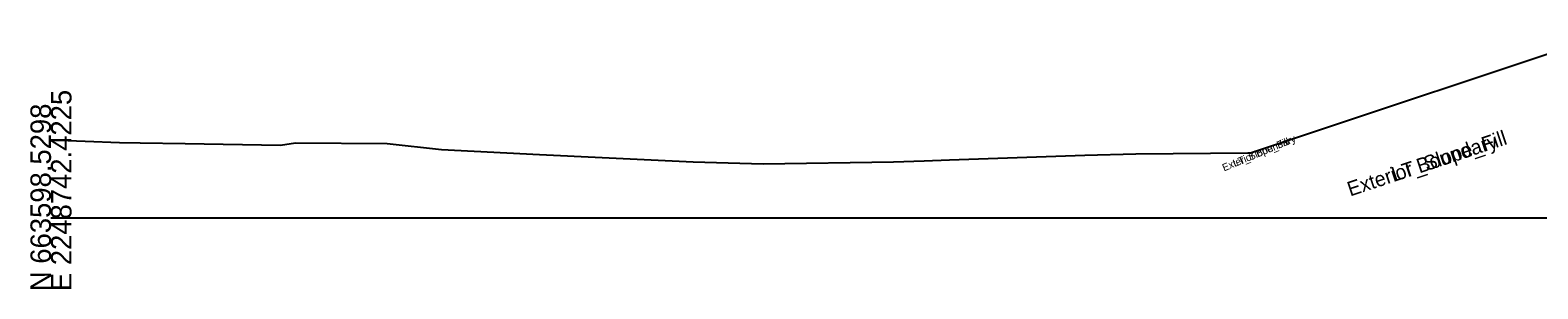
# Model space of a CAD drawing. Extents: x -26 to 2603, y -10 to 9566.
# Drawn here: x 997.2 to 1203, y 2990.3 to 3025.6 of the extents above; entities that cross this region are included whole.
import ezdxf

# ---------------------------------------------------------------- set-up
doc = ezdxf.new("R2010")
doc.units = 0
for name, color, linetype in [('Default', 7, 'Continuous'), ('Exist Cross Section Cell', 7, 'Continuous'), ('Exist XS Ground Line', 7, 'Continuous'), ('Scratch_Level_9', 7, 'Continuous')]:
    doc.layers.add(name, color=color, linetype=linetype)

msp = doc.modelspace()

# ---------------------------------------------------------------- linework, layer by layer
at = {"layer": 'Exist Cross Section Cell'}
msp.add_line((1000, 3000), (1300, 3000), dxfattribs=at)
at = {"layer": 'Exist XS Ground Line'}
for p, q in [((1000, 3010.64), (1009.37, 3010.3)), ((1009.37, 3010.3), (1012.17, 3010.27)), ((1012.17, 3010.27), (1018.32, 3010.14)), ((1018.32, 3010.14), (1031.34, 3009.93)), ((1031.34, 3009.93), (1033.38, 3010.23)), ((1033.38, 3010.23), (1045.92, 3010.16)), ((1045.92, 3010.16), (1053.3, 3009.35)), ((1053.3, 3009.35), (1066.68, 3008.67)), ((1066.68, 3008.67), (1075.27, 3008.24)), ((1075.27, 3008.24), (1087.69, 3007.67)), ((1087.69, 3007.67), (1097.24, 3007.36)), ((1097.24, 3007.36), (1115.04, 3007.67)), ((1115.04, 3007.67), (1119.2, 3007.78)), ((1119.2, 3007.78), (1122.67, 3007.91)), ((1122.67, 3007.91), (1141.17, 3008.55)), ((1141.17, 3008.55), (1148.11, 3008.75)), ((1148.11, 3008.75), (1163.4, 3008.9)), ((1163.4, 3008.9), (1163.9, 3008.88))]:
    msp.add_line(p, q, dxfattribs=at)
msp.add_lwpolyline([(1214.18, 3025.64), (1163.9, 3008.88)], dxfattribs=at)

# ---------------------------------------------------------------- texts
at = {"layer": 'Default'}
msp.add_text('-', height=0.0001, dxfattribs=at).set_placement((1000, 3000))
msp.add_text('-', height=0.0001, dxfattribs=at).set_placement((1000, 3000))
msp.add_text('-', height=0.0001, dxfattribs=at).set_placement((1000, 3000))
msp.add_text('-', height=0.0001, dxfattribs=at).set_placement((1000, 3000))
msp.add_text('-', height=0.0001, dxfattribs=at).set_placement((1000, 3000))
at = {"layer": 'Exist Cross Section Cell'}
for s, p in [('E 2248742.4225', (1002.8, 2990)), ('N 663598.5298', (1000, 2990))]:
    msp.add_text(s, height=2.8, rotation=90, dxfattribs=at).set_placement(p)
at = {"layer": 'Scratch_Level_9'}
for s, height, rotation, p in [('LT_Slope_Fill', 2, 18.4332, (1183.44, 3004.93)), ('LT_Slope_Fill', 2, 18.4332, (1183.44, 3004.93)), ('Exterior Boundary', 1, 22.5575, (1160.17, 3006.34)), ('LT_Slope_Fill', 1, 22.5575, (1161.63, 3006.94)), ('Exterior Boundary', 2, 18.4332, (1177.39, 3002.91)), ('Exterior Boundary', 2, 18.4332, (1177.39, 3002.91))]:
    msp.add_text(s, height=height, rotation=rotation, dxfattribs=at).set_placement(p)

doc.saveas('drawing.dxf')
